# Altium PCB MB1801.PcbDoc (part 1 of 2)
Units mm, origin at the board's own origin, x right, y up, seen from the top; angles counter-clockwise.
Board outline 70.1 x 57.1 mm, 2 copper layers (Top Layer, Bottom Layer), stack 1.554 mm thick; 124 components, 115 nets, 557 pads, 485 vias.
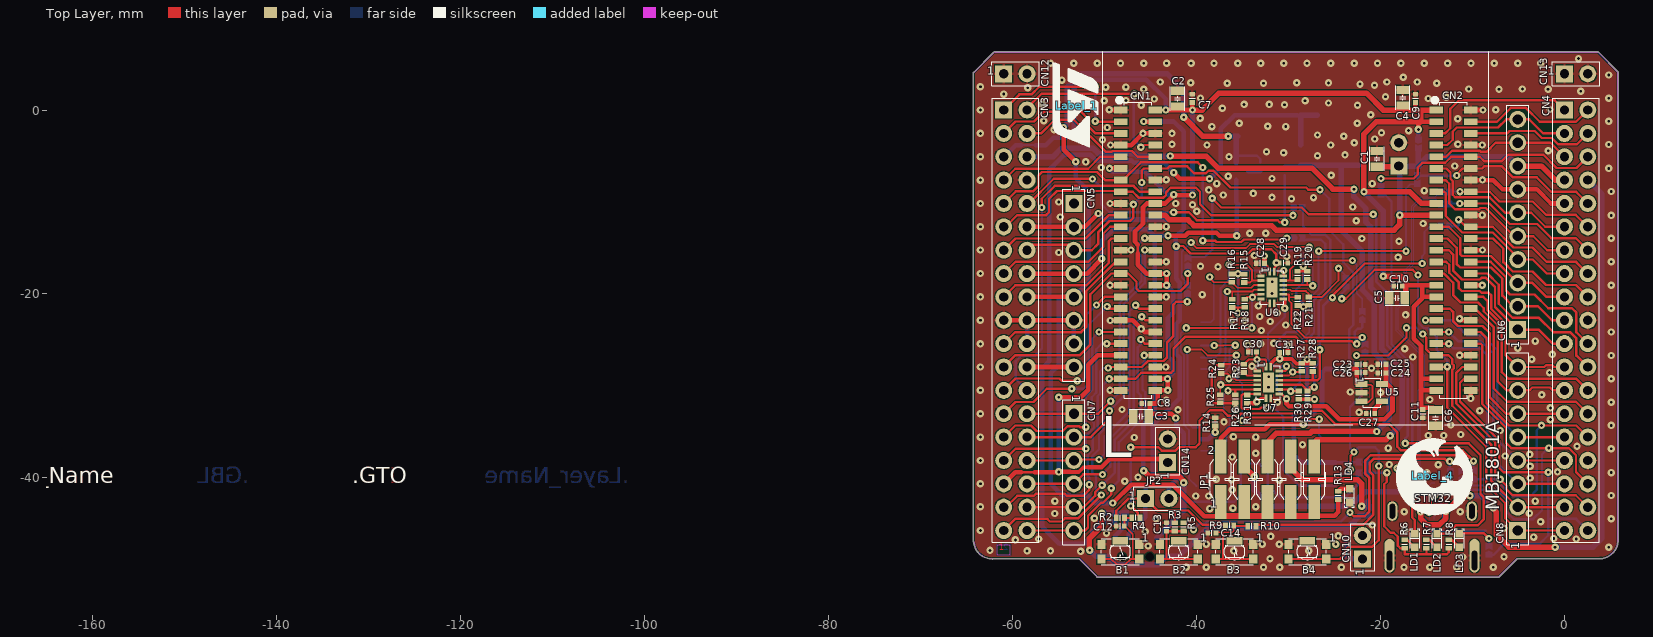
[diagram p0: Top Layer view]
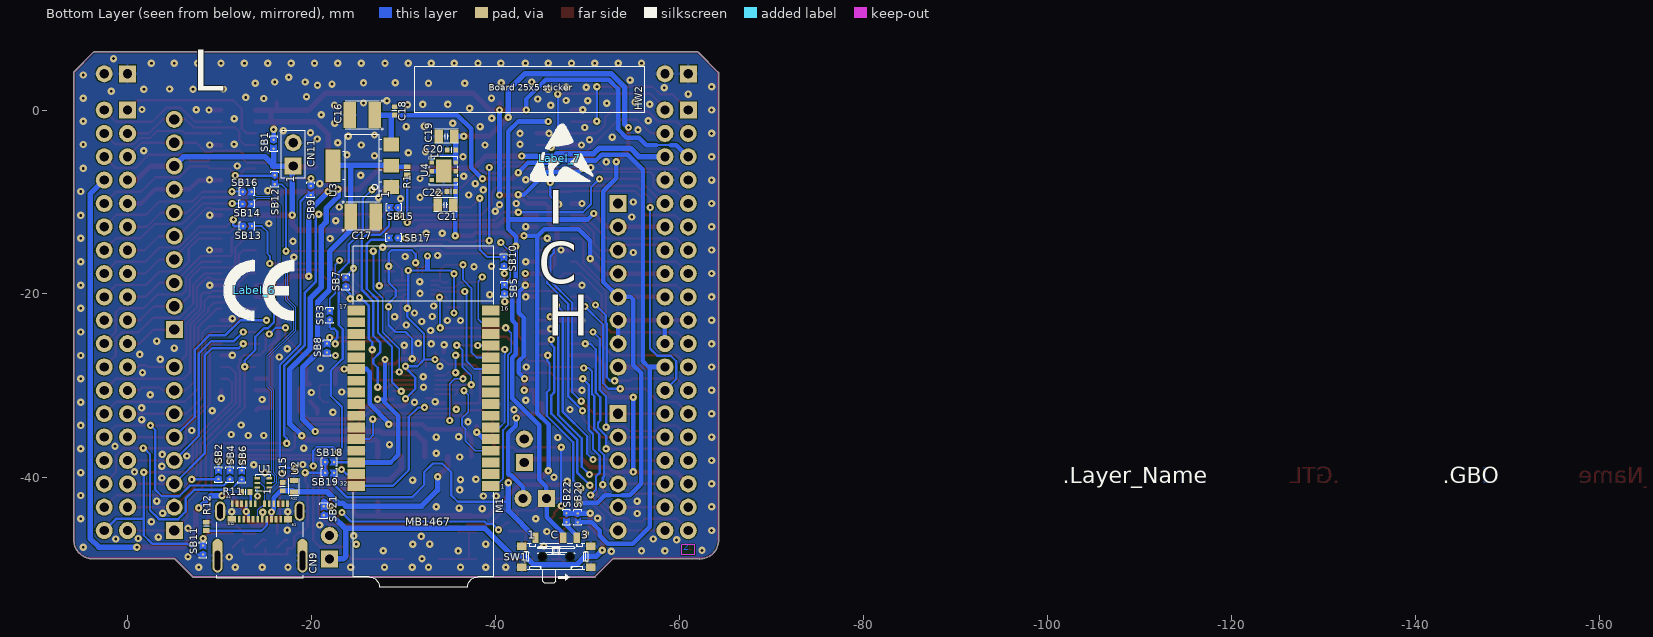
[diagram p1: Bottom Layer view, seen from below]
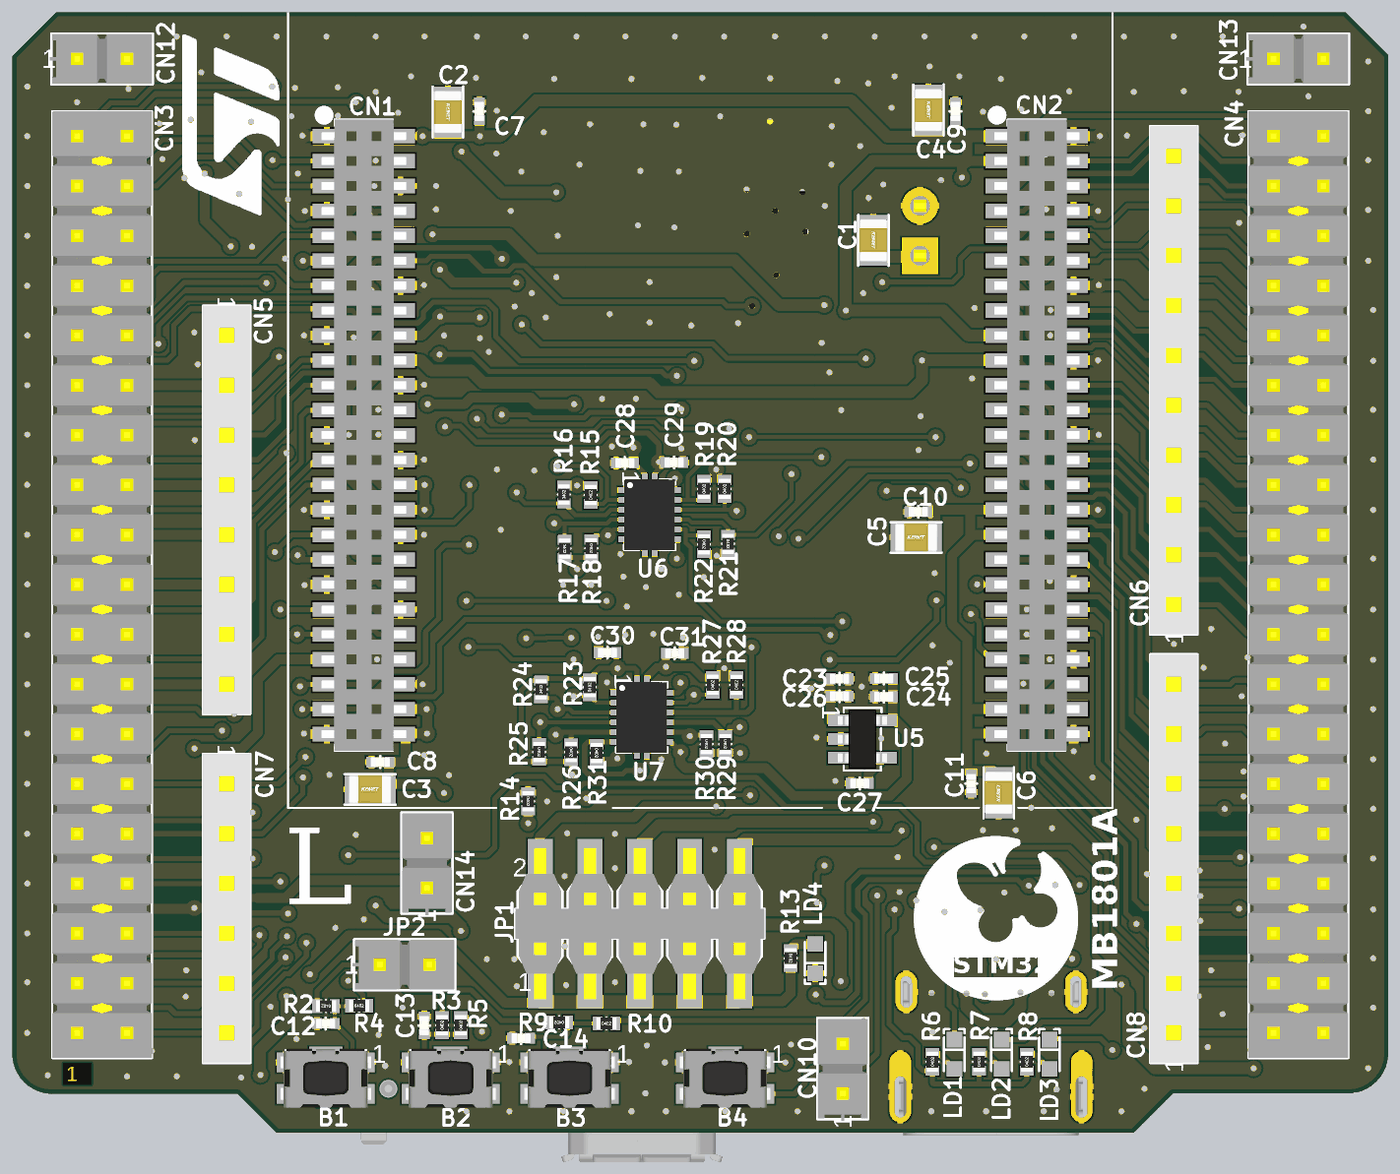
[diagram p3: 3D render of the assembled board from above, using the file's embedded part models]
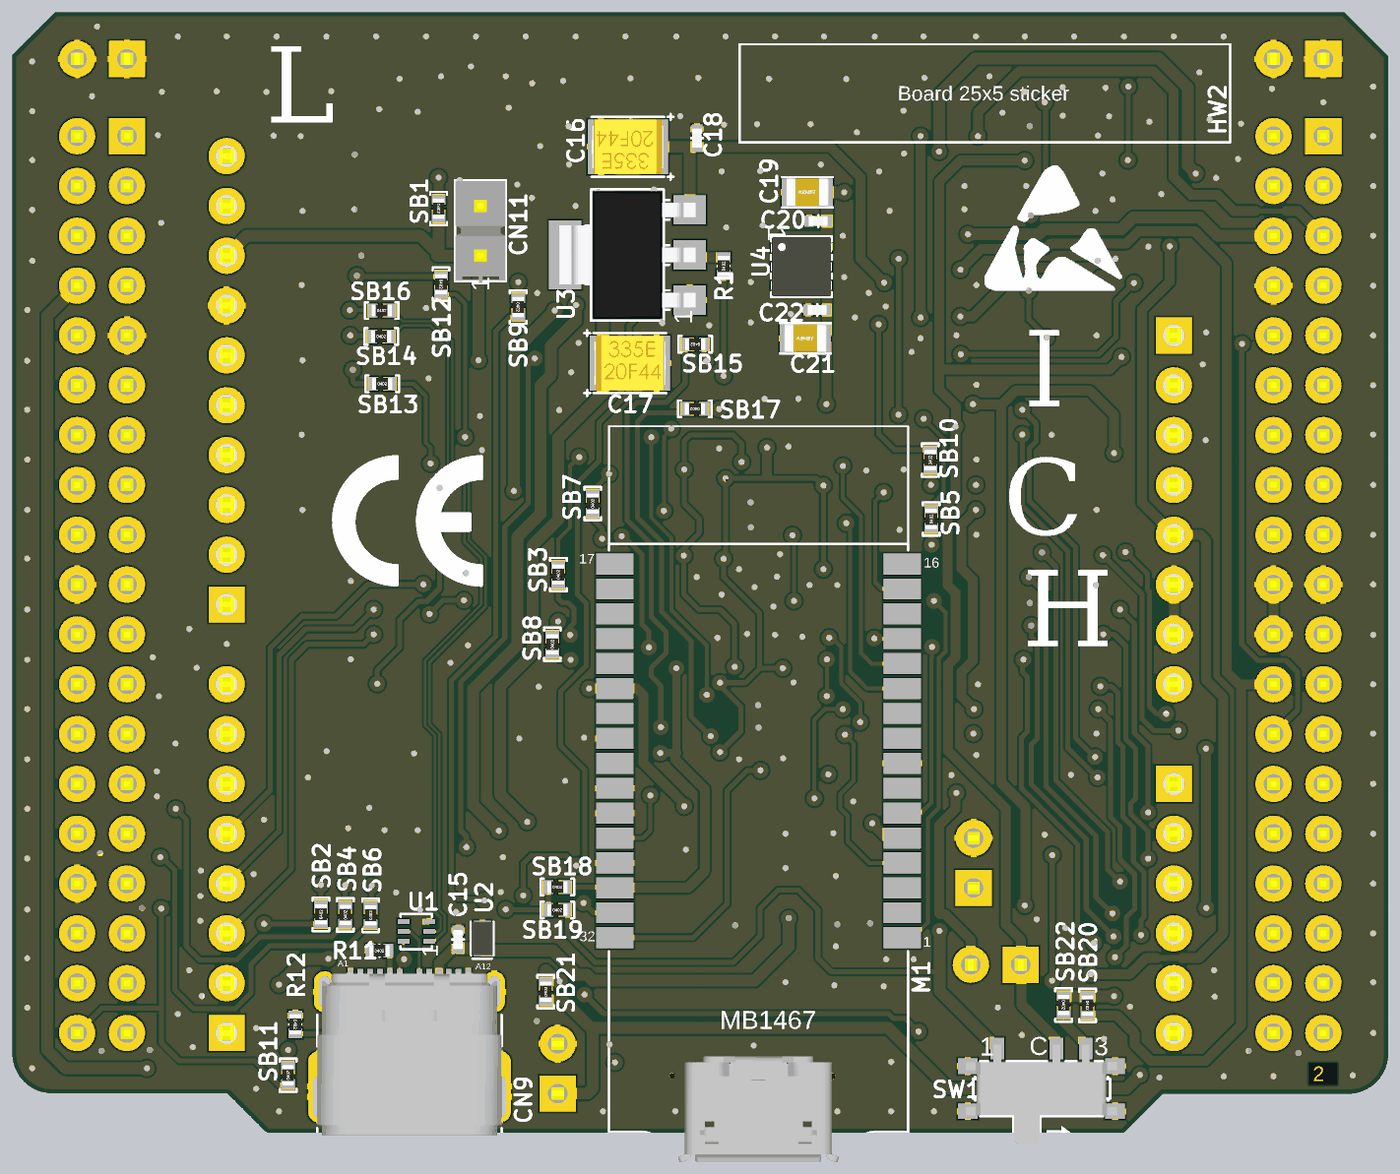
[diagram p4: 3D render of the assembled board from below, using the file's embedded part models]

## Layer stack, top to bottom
Top Solder: solder mask 0.0178, Solder Resist, Dk 4.2
Top Layer: signal copper 0.0406
Dielectric 1: dielectric 1.4732, FR-4, Dk 4.4
Bottom Layer: signal copper 0.0406
Bottom Solder: solder mask 0.0178, Solder Resist, Dk 4.2

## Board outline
-62.21,-48.818 ccw(c-62.21,-48.768) -62.183,-48.81 -52.79,-48.81 -50.822,-50.778 ccw(c-50.786,-50.743) -50.786,-50.793 -7.131,-50.793 ccw(c-7.131,-50.743) -7.095,-50.778 -5.11,-48.793 3.79,-48.793 ccw(c3.79,-46.743) 5.84,-46.743 ccw(c5.79,-46.743) 5.84,-46.742 5.84,2.211 5.84,4.125 ccw(c5.79,4.125) 5.825,4.161 5.826,4.16 3.693,6.293 3.694,6.292 ccw(c3.658,6.257) 3.658,6.307 -62.001,6.307 ccw(c-62.001,6.257) -62.037,6.292 -62.037,6.293 -64.246,4.084 -64.245,4.084 ccw(c-64.21,4.048) -64.26,4.048 -64.26,-46.768 ccw(c-64.21,-46.768) -64.26,-46.769 cw(c-62.21,-46.768) -64.26,-46.768 -64.26,-46.769 ccw(c-62.21,-46.768)

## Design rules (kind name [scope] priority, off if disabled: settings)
Clearance [All] p1: gap=0.1 ignorepadtopadclearanceinfootprint=FALSE
ComponentClearance [All] p1: gap=0.2 collisioncheckmode=3 verticalgap=0.2 showdistances=FALSE
DiffPairsRouting [All] p1: maxlimit=0.102 minlimit=0.102 mostfreqgap=0.102 toplayer_minwidth=0.12 toplayer_maxwidth=0.12 toplayer_prefwidth=0.12 bottomlayer_minwidth=0.12 bottomlayer_maxwidth=0.12 bottomlayer_prefwidth=0.12 maxuncoupledlength=12.7
HoleSize [All] p1: absolutevalues=TRUE maxlimit=10 minlimit=0.025 maxpercent=80.000 minpercent=20.000
MatchedLengths "Schematic Matched Net Lengths_3" [InNet('USB_C_N')] p1: tolerance=2 checknetsindiffpair=TRUE checkdiffpairvsdiffpair=FALSE checkxsignals=FALSE checkothers=FALSE
MatchedLengths "Schematic Matched Net Lengths_2" [InNet('USB_C_P')] p2: tolerance=2 checknetsindiffpair=TRUE checkdiffpairvsdiffpair=FALSE checkxsignals=FALSE checkothers=FALSE
MatchedLengths "Schematic Matched Net Lengths_1" [InNet('USB_P')] p3: tolerance=2 checknetsindiffpair=TRUE checkdiffpairvsdiffpair=FALSE checkxsignals=FALSE checkothers=FALSE
MatchedLengths "Schematic Matched Net Lengths" [InNet('USB_N')] p4: tolerance=2 checknetsindiffpair=TRUE checkdiffpairvsdiffpair=FALSE checkxsignals=FALSE checkothers=FALSE
MaxMinImpedance "Schematic Impedance Constraint_8" [InNet('USB_C_P')] p1: minimum=85,00 maximum=95,00
MaxMinImpedance "Schematic Impedance Constraint_7" [InNet('USB_P')] p2: minimum=85,00 maximum=95,00
MaxMinImpedance "Schematic Impedance Constraint_6" [InNet('USB_C_N')] p3: minimum=85,00 maximum=95,00
MaxMinImpedance "Schematic Impedance Constraint" [InNet('USB_N')] p4: minimum=85,00 maximum=95,00
MinimumSolderMaskSliver [All] p1: minsoldermaskwidth=0.1
PlaneConnect [All] p1: planeconnectstyle=Direct reliefexpansion=0.508 reliefentries=4 reliefconductorwidth=0.21 reliefairgap=0.21
PolygonConnect PolygonConnect_via [IsVia] p1: connectstyle=Direct reliefconductorwidth=0.254 reliefentries=4 polygonreliefangle="90 Angle" airgapwidth=0.254
PolygonConnect [All] p2: connectstyle=Relief reliefconductorwidth=0.3 reliefentries=4 polygonreliefangle="90 Angle" airgapwidth=0.1
RoutingVias [All] p1: holewidth=0.3 width=0.8 viastyle="Through Hole" minholewidth=0.3 minwidth=0.8 maxholewidth=0.3 maxwidth=0.8
SilkToSilkClearance [All] p1: silktosilkclearance=0.2
SilkToSolderMaskClearance [IsPad] p1: minsilkscreentomaskgap=0.2 clearancetoexposedcopper=TRUE
SolderMaskExpansion [All] p1: expansion=0.102 istentingtop=FALSE
Width [All] p1: maxlimit=1 minlimit=0.2 preferedwidth=0.2 minimp=50.000000 maximp=50.000000 favimp=50.000000
23 further rules are at their usual default settings.

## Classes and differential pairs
component class Project_Overview: HW1 HW2
component class "STLINK-V3MODS & Level Shifter": C23 C24 C25 C26 C27 C28 C29 C30 C31 M1 R14 R15 R16 R17 R18 R19 R20 R21 R22 R23 R24 R25 R26 R27 R28 R29 R30 R31 U5 U6 U7
component class "Power Management": C16 C17 C18 C19 C20 C21 C22 CN10 CN12 CN13 HW1 JP1 JP2 LD4 R13 SB20 SB21 SB22 SW1 U3 U4
component class "LEDs & Push Buttons & USB-C Connector": B1 B2 B3 B4 C12 C13 C14 C15 CN9 LD1 LD2 LD3 R2 R3 R4 R5 R6 R7 R8 R9 R10 R11 R12 SB18 SB19 U1 U2
component class "Extension Connectors": C1 C2 C3 C4 C5 C6 C7 C8 C9 C10 C11 CN1 CN2 CN3 CN4 CN5 CN6 CN7 CN8 CN11 CN14 R1 SB1 SB2 SB3 SB4 SB5 SB6 SB7 SB8 SB9 SB10 SB11 SB12 SB13 SB14 SB15 SB16 SB17
differential pair USB: +USB_P -USB_N
differential pair USB_C: +USB_C_P -USB_C_N

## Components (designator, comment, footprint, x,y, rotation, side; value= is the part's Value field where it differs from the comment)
B1 "SW-PUSH-CMS_KMR2_BLACK" SWI_C&K_Y78B23110FP__ITT_KMR231GLFS -48.29,-48.022 r0 top value=KMR231GLFS
B2 "SW-PUSH-CMS_KMR2_BLACK" SWI_C&K_Y78B23110FP__ITT_KMR231GLFS -41.93,-48.022 r0 top value=KMR231GLFS
B3 "SW-PUSH-CMS_KMR2_BLACK" SWI_C&K_Y78B23110FP__ITT_KMR231GLFS -35.871,-48.022 r0 top locked value=KMR231GLFS
B4 "SW-PUSH-CMS_KMR2_BLACK" SWI_C&K_Y78B23110FP__ITT_KMR231GLFS -27.946,-48.022 r0 top locked value=KMR231GLFS
C1 "Capacitor" C0805_H0P85 -20.387,-5.308 r270 top value=1uF
C2 "Capacitor" C0805_H0P85 -42.066,1.23 r270 top value=1uF
C3 "Capacitor" C0805_H0P85 -46.035,-33.303 r0 top value=1uF
C4 "Capacitor" C0805_H0P85 -17.58,1.331 r270 top value=1uF
C5 "Capacitor" C0805_H0P85 -18.207,-20.457 r0 top value=1uF
C6 "Capacitor" C0805_H0P85 -13.999,-33.472 r90 top value=1uF
C7 "Capacitor" C0402 -40.464,1.268 r270 top value=100nF
C8 "Capacitor" C0402 -45.514,-31.904 r0 top value=100nF
C9 "Capacitor" C0402 -16.207,1.268 r270 top value=100nF
C10 "Capacitor" C0402 -18.1,-19.146 r0 top value=100nF
C11 "Capacitor" C0402 -15.403,-33.003 r90 top value=100nF
C12 "Capacitor" C0402 -48.293,-45.236 r0 top value=10nF
C13 "Capacitor" C0402 -43.272,-45.336 r270 top value=10nF
C14 "Capacitor" C0402 -38.339,-45.984 r0 top value=10nF
C15 "Capacitor" C0402 -16.87,-40.95 r270 bottom value=100pF
C16 "Cap_POL_TANA" CPOL_TAJ-B_1210_H210 -25.521,-0.546 r0 bottom value=10uF
C17 "Cap_POL_TANA" CPOL_TAJ-B_1210_H210 -25.621,-11.567 r180 bottom value=10uF
C18 "Capacitor" C0402 -29.046,-0.101 r270 bottom value=100nF
C19 "Capacitor" C0805_H0P85 -34.671,-2.864 r180 bottom value=1uF
C20 "Capacitor" C0402 -35.221,-4.332 r180 bottom value=100nF
C21 "Capacitor" C0805_H0P85 -34.569,-10.308 r180 bottom value=1uF
C22 "Capacitor" C0402 -35.171,-8.859 r180 bottom value=100nF
C23 "Capacitor" C0402 -22.113,-27.661 r180 top value=1uF
C24 "Capacitor" C0402 -19.852,-28.575 r0 top value=1uF
C25 "Capacitor" C0402 -19.852,-27.643 r0 top value=100nF
C26 "Capacitor" C0402 -22.113,-28.55 r180 top value=100nF
C27 "Capacitor" C0402 -21.082,-32.995 r0 top value=100nF
C28 "Capacitor" C0402 -33.049,-16.656 r180 top value=100nF
C29 "Capacitor" C0402 -30.54,-16.63 r180 top value=100nF
C30 "Capacitor" C0402 -33.935,-26.327 r180 top value=100nF
C31 "Capacitor" C0402 -30.51,-26.362 r180 top value=100nF
CN1 "CLP-125-02-F-D" CLP-125-02-F-D -46.355,-15.24 r0 top locked
CN2 "CLP-125-02-F-D" CLP-125-02-F-D -12.065,-15.24 r0 top locked
CN3 "Header 19x2" CON_SAMTEC_TSW-119-09-X-D -59.69,-22.86 r270 top locked
CN4 "Header 19x2" CON_SAMTEC_TSW-119-09-X-D 1.27,-22.86 r270 top locked
CN5 "Socket 8x1" CON_SAMTEC_SSW-108-01-X-S -53.34,-19.05 r270 top locked
CN6 "Socket 10x1" CON_SAMTEC_SSW-110-01-X-S -5.08,-12.446 r90 top locked
CN7 "Socket 6x1" CON_SAMTEC_SSW-106-01-X-S -53.34,-39.37 r270 top locked
CN8 "Socket 8x1" CON_SAMTEC_SSW-108-01-X-S -5.08,-36.83 r90 top locked
CN9 "USB_TYPE_C_Receptacle" CON_USB-TYPEC_MOLEX_2012670005 -14.392,-45.892 r180 bottom value=USB_C_2012670005
CN10 "Header 2x1" CON_SAMTEC_TSW-102-07-G-S -21.949,-47.535 r90 top
CN11 "Header 2x1" CON_SAMTEC_TSW-102-07-G-S -18.013,-4.823 r90 bottom
CN12 "Header 2x1" CON_SAMTEC_TSW-102-07-G-S -59.69,3.937 r0 top
CN13 "Header 2x1" CON_SAMTEC_TSW-102-07-G-S 1.27,3.937 r0 top locked
CN14 "Header 2x1" CON_SAMTEC_TSW-102-07-G-S -43.135,-37.049 r90 top
HW2 "STICKER_BOARD" STICKER_BOARD_25X5 -43.711,2.183 r180 bottom value="Sticker board"
JP1 "Jumper_Header 5x2 Fitted 1-2" CON_SAMTEC_TSM-105-01-L-DV -32.288,-40.146 r0 top value="Header 5x2"
JP2 "Jumper_Header 2x1 Fitted" CON_SAMTEC_TSW-102-07-G-S -44.271,-42.237 r0 top value="Header 2x1"
Label_1 "LOGO_ST" LOGO_ST_Size3 -53.029,0.465 r90 top
Label_4 "LOGO_STM32" LOGO_STM32 -14.298,-39.75 r0 top
Label_6 "LOGO_CE" "LOGO CE" -13.764,-19.607 r180 bottom
Label_7 "LOGO_ESD" "LOGO ESD" -46.982,-5.223 r180 bottom
LD1 "LED_blue" LED_0603_VISHAY_VLMB1300-GS08_BLUE_1A2K_H0P8 -16.266,-46.8 r90 top value=BLUE
LD2 "LED_green" LED_0603_VISHAY_VLMTG1300-GS08_GREEN_1A2K_H0P8 -13.852,-46.8 r90 top value="TRUE GREEN"
LD3 "LED_red" LED_0603_VISHAY_VLMS1300-GS08_RED_1A2K_H0P8 -11.424,-46.8 r90 top value=RED
LD4 "LED_green" LED_0603_VISHAY_VLMTG1300-GS08_GREEN_1A2K_H0P8 -23.355,-41.931 r270 top value="TRUE GREEN"
M1 "STLINK-V3MODS" MOD_STLINK-V3M_MB1467_TYPEC -32.178,-31.334 r180 bottom locked
R1 "Resistor" R0402 -30.397,-6.623 r90 bottom value=1K
R2 "Resistor" R0402 -48.278,-44.343 r180 top value=10K
R3 "Resistor" R0402 -42.365,-45.321 r90 top value=10K
R4 "Resistor" R0402 -46.591,-44.324 r0 top value=1K
R5 "Resistor" R0402 -41.408,-45.319 r90 top value=1K
R6 "Resistor" R0402 -17.374,-47.185 r90 top value=680R
R7 "Resistor" R0402 -15.006,-47.184 r90 top value=680R
R8 "Resistor" R0402 -12.577,-47.185 r90 top value=680R
R9 "Resistor" R0402 -36.398,-45.173 r180 top value=10K
R10 "Resistor" R0402 -33.989,-45.232 r0 top value=1K
R11 "Resistor" R0402 -12.865,-41.53 r180 bottom value=5K1
R12 "Resistor" R0402 -8.57,-45.275 r270 bottom value=5K1
R13 "Resistor" R0402 -24.6,-41.902 r270 top value=1K
R14 "Resistor" R0402 -37.978,-33.907 r270 top value=100R
R15 "Resistor" R0402 -34.796,-18.293 r90 top value=100K
R16 "Resistor" R0402 -36.158,-18.268 r90 top value=100K
R17 "Resistor" R0402 -36.122,-21.024 r270 top value=100K
R18 "Resistor" R0402 -34.76,-21.009 r270 top value=100K
R19 "Resistor" R0402 -29.021,-17.977 r90 top value=100K
R20 "Resistor" R0402 -27.969,-17.978 r90 top value=100K
R21 "Resistor" R0402 -27.793,-20.782 r270 top value=100K
R22 "Resistor" R0402 -29.015,-20.807 r270 top value=100K
R23 "Resistor" R0402 -34.846,-28.092 r90 top value=100K
R24 "Resistor" R0402 -37.329,-28.201 r90 top value=100K
R25 "Resistor" R0402 -37.417,-31.392 r270 top value=100K
R26 "Resistor" R0402 -35.784,-31.401 r270 top value=100K
R27 "Resistor" R0402 -28.58,-27.967 r90 top value=100K
R28 "Resistor" R0402 -27.374,-27.976 r90 top value=100K
R29 "Resistor" R0402 -27.935,-30.992 r270 top value=100K
R30 "Resistor" R0402 -28.889,-30.992 r270 top value=100K
R31 "Resistor" R0402 -34.491,-31.442 r270 top value=100K
SB1 "SB_ON" SOLDER-BRIDGE_R0402-0R -15.878,-3.692 r270 bottom
SB2 "SB_ON" SOLDER-BRIDGE_R0402-0R -9.884,-39.672 r90 bottom
SB3 "SB_ON" SOLDER-BRIDGE_R0402-0R -21.98,-22.35 r90 bottom
SB4 "SB_ON" SOLDER-BRIDGE_R0402-0R -11.123,-39.697 r90 bottom
SB5 "SB_ON" SOLDER-BRIDGE_R0402-0R -40.979,-19.516 r90 bottom
SB6 "SB_ON" SOLDER-BRIDGE_R0402-0R -12.416,-39.718 r90 bottom
SB7 "SB_OFF" SOLDER-BRIDGE_R0402-0R -23.733,-18.729 r90 bottom value=SB0402
SB8 "SB_OFF" SOLDER-BRIDGE_R0402-0R -21.675,-25.904 r90 bottom value=SB0402
SB9 "SB_ON" SOLDER-BRIDGE_R0402-0R -19.932,-8.712 r270 bottom
SB10 "SB_ON" SOLDER-BRIDGE_R0402-0R -40.931,-16.513 r90 bottom
SB11 "SB_ON" SOLDER-BRIDGE_R0402-0R -8.211,-47.869 r90 bottom
SB12 "SB_OFF" SOLDER-BRIDGE_R0402-0R -16.002,-7.544 r270 bottom value=SB0402
SB13 "SB_OFF" SOLDER-BRIDGE_R0402-0R -13.005,-12.624 r180 bottom value=SB0402
SB14 "SB_OFF" SOLDER-BRIDGE_R0402-0R -12.954,-10.211 r180 bottom value=SB0402
SB15 "SB_ON" SOLDER-BRIDGE_R0402-0R -28.956,-10.608 r0 bottom
SB16 "SB_OFF" SOLDER-BRIDGE_R0402-0R -12.979,-8.89 r180 bottom value=SB0402
SB17 "SB_ON" SOLDER-BRIDGE_R0402-0R -28.936,-13.901 r0 bottom
SB18 "SB_ON" SOLDER-BRIDGE_R0402-0R -21.93,-38.278 r180 bottom
SB19 "SB_OFF" SOLDER-BRIDGE_R0402-0R -21.93,-39.446 r180 bottom value=SB0402
SB20 "SB_OFF" SOLDER-BRIDGE_R0402-0R -48.943,-44.311 r270 bottom value=SB0402
SB21 "SB_OFF" SOLDER-BRIDGE_R0402-0R -21.339,-43.61 r90 bottom value=SB0402
SB22 "SB_OFF" SOLDER-BRIDGE_R0402-0R -47.724,-44.29 r270 bottom value=SB0402
SW1 "SW_MECA" SWI_SPDT-RA_TE-CONNECTIVITY_MLL1200S_1P2T -46.6,-48.559 r180 bottom locked value=Switch-Slider_3x1_MLL1200S
U1 "ECMF02-2AMX6" ESD_QFN-6L_1P7X1P5_P050 -14.741,-40.55 r90 bottom
U2 "ESD-TRANSIL" ESD_QFN1610_2N_1K_2A -18.1,-40.9 r90 bottom value=ESDA25P35-1U1M
U3 "LD1117S50TR" REG_SOT223-TAB -25.496,-6.057 r90 bottom
U4 "LD39050PU33R" ICC_DFN6-EPAD_3X3_P095 -34.371,-6.655 r270 bottom
U5 "LD3985M33R" REG_SOT23-5L -20.948,-30.738 r270 top
U6 "74AVC4TD245BQ" ICC_DHVQFN16-EPAD_SOT763-1_2P5X3P5_H0P85_P050 -31.79,-19.291 r0 top
U7 "74AVC4TD245BQ" ICC_DHVQFN16-EPAD_SOT763-1_2P5X3P5_H0P85_P050 -32.19,-29.63 r0 top
? "Comment" PCB_SPECIFICATIONS -182.118,65.278 r0 top
? "Comment" Sheetbox_2L2S -182.474,-52.857 r0 top

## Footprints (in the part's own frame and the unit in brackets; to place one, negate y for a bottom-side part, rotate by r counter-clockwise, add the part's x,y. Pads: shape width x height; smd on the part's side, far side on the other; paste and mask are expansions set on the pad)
C0402 [mm]
  rect 0.51x0.56 smd mask+0.05: 1(-0.45,0) 2(0.45,0)
  silkscreen extent 0,-0.3 0,0.3, body extent -0.5,-0.3 0.5,0.3, height 0.4
C0805_H0P85 [mm] "MCD-01525"
  rect 0.9x1.4 smd mask+0.05: 1(-0.85,0) 2(0.85,0)
  silkscreen extent -1.3,-0.77 1.3,0.77, body extent -1.1,-0.73 1.1,0.73, height 0.95
CLP-125-02-F-D [mm] "Socket 2x25 1.27mm SAMTEC (CLP-125-02-F-D)"
  rect 1.47x0.74 smd: 1(-1.87,15.24) 2(1.87,15.24) 3(-1.87,13.97) 4(1.87,13.97) 5(-1.87,12.7) 6(1.87,12.7) 7(-1.87,11.43) 8(1.87,11.43) 9(-1.87,10.16) 10(1.87,10.16) 11(-1.87,8.89) 12(1.87,8.89) 13(-1.87,7.62) 14(1.87,7.62) 15(-1.87,6.35) 16(1.87,6.35) 17(-1.87,5.08) 18(1.87,5.08) 19(-1.87,3.81) 20(1.87,3.81) 21(-1.87,2.54) 22(1.87,2.54) 23(-1.87,1.27) 24(1.87,1.27) 25(-1.87,0) 26(1.87,0) 27(-1.87,-1.27) 28(1.87,-1.27) 29(-1.87,-2.54) 30(1.87,-2.54) 31(-1.87,-3.81) 32(1.87,-3.81) 33(-1.87,-5.08) 34(1.87,-5.08) 35(-1.87,-6.35) 36(1.87,-6.35) 37(-1.87,-7.62) 38(1.87,-7.62) 39(-1.87,-8.89) 40(1.87,-8.89) 41(-1.87,-10.16) 42(1.87,-10.16) 43(-1.87,-11.43) 44(1.87,-11.43) 45(-1.87,-12.7) 46(1.87,-12.7) 47(-1.87,-13.97) 48(1.87,-13.97) 49(-1.87,-15.24) 50(1.87,-15.24)
  silkscreen extent -2.25,-16.09 1.49,16.54, body extent -2.15,-16.09 2.17,16.09, height 2.27
CON_SAMTEC_SSW-106-01-X-S [mm] "MCD-02079"
  rect 1.85x1.85 / inner round 1.85 / far side rect 1.85x1.85 hole 1.1 mask+0.05: 1(-6.35,0)
  round 1.85 hole 1.1 mask+0.05: 2(-3.81,0) 3(-1.27,0) 4(1.27,0) 5(3.81,0) 6(6.35,0)
  silkscreen extent -7.88,-1.2 7.88,1.2, body extent -7.88,-1.21 7.88,1.21, height 8.51
CON_SAMTEC_SSW-108-01-X-S [mm] "MCD-01743"
  rect 1.85x1.85 / inner round 1.85 / far side rect 1.85x1.85 hole 1.1 mask+0.05: 1(-8.89,0)
  round 1.85 hole 1.1 mask+0.05: 2(-6.35,0) 3(-3.81,0) 4(-1.27,0) 5(1.27,0) 6(3.81,0) 7(6.35,0) 8(8.89,0)
  silkscreen extent -10.42,-1.2 10.42,1.2, body extent -10.42,-1.21 10.42,1.21, height 8.51
CON_SAMTEC_SSW-110-01-X-S [mm] "MCD-02080"
  rect 1.85x1.85 / inner round 1.85 / far side rect 1.85x1.85 hole 1.1 mask+0.05: 1(-11.43,0)
  round 1.85 hole 1.1 mask+0.05: 2(-8.89,0) 3(-6.35,0) 4(-3.81,0) 5(-1.27,0) 6(1.27,0) 7(3.81,0) 8(6.35,0) 9(8.89,0) 10(11.43,0)
  silkscreen extent -12.96,-1.2 12.96,1.2, body extent -12.96,-1.21 12.96,1.21, height 8.51
CON_SAMTEC_TSM-105-01-L-DV [mm]
  rect 1.27x3.68 smd paste+0 mask+0.05: 1(-5.08,-2.475) 2(-5.08,2.475) 3(-2.54,-2.475) 4(-2.54,2.475) 5(0,-2.475) 6(0,2.475) 7(2.54,-2.475) 8(2.54,2.475) 9(5.08,-2.475) 10(5.08,2.475)
  silkscreen extent -6.35,-2.16 6.35,2.16, body extent -6.35,-3.85 6.35,3.85, height 9.65
CON_SAMTEC_TSW-102-07-G-S [mm]
  rect 1.85x1.85 / inner round 1.85 / far side rect 1.85x1.85 hole 1 mask+0.05: 1(-1.27,0)
  round 1.85 hole 1 mask+0.05: 2(1.27,0)
  silkscreen extent -2.58,-1.3 2.58,1.3, body extent -2.67,-1.3 2.58,1.3, height 8.38
CON_SAMTEC_TSW-119-09-X-D [mm]
  rect 1.85x1.85 / inner round 1.85 / far side rect 1.85x1.85 hole 1 mask+0.05: 1(-22.86,-1.27)
  round 1.85 hole 1 mask+0.05: 2(-22.86,1.27) 3(-20.32,-1.27) 4(-20.32,1.27) 5(-17.78,-1.27) 6(-17.78,1.27) 7(-15.24,-1.27) 8(-15.24,1.27) 9(-12.7,-1.27) 10(-12.7,1.27) 11(-10.16,-1.27) 12(-10.16,1.27) 13(-7.62,-1.27) 14(-7.62,1.27) 15(-5.08,-1.27) 16(-5.08,1.27) 17(-2.54,-1.27) 18(-2.54,1.27) 19(0,-1.27) 20(0,1.27) 21(2.54,-1.27) 22(2.54,1.27) 23(5.08,-1.27) 24(5.08,1.27) 25(7.62,-1.27) 26(7.62,1.27) 27(10.16,-1.27) 28(10.16,1.27) 29(12.7,-1.27) 30(12.7,1.27) 31(15.24,-1.27) 32(15.24,1.27) 33(17.78,-1.27) 34(17.78,1.27) 35(20.32,-1.27) 36(20.32,1.27) 37(22.86,-1.27) 38(22.86,1.27)
  silkscreen extent -24.13,-2.54 24.13,2.54, body extent -24.13,-2.55 24.13,2.54, height 8.38
CON_USB-TYPEC_MOLEX_2012670005 [mm] "MCD-02421"
  rect 0.3x0.7 smd mask+0.05: A1(-3,3.085) A2(-2.5,3.085) A3(-2,3.085) A4(-1.5,3.085) A5(-1,3.085) A6(-0.5,3.085) A7(0.5,3.085) A8(1,3.085) A9(1.5,3.085) A10(2,3.085) A11(2.5,3.085) A12(3,3.085) B2(2.25,1.385) B3(1.75,1.385) B4(1.25,1.385) B5(0.75,1.385) B6(0.25,1.385) B7(-0.25,1.385) B8(-0.75,1.385) B9(-1.25,1.385) B10(-1.75,1.385) B11(-2.25,1.385)
  rect 0.9x0.7 smd mask+0.05: B1(3.05,1.385) B12(-3.05,1.385)
  oval 1.1x2.1 hole 0.6 slot 1.6 at 90 deg mask+0.05: SH1(-4.32,2.275) SH2(4.32,2.275)
  oval 1.1x2.6 hole 0.6 slot 2.1 at 90 deg mask+0.05: SH3(-4.62,-3.085) SH4(4.62,-3.085)
  oval 1.1x3.6 all layers, no hole mask+0.05: SH3(-4.62,-2.55) SH4(4.62,-2.55)
  silkscreen extent -4.7,-5.02 4.7,1.1, body extent -4.7,-5.03 4.69,3.27, height 3.67
CPOL_TAJ-B_1210_H210 [mm]
  rect 1.35x2.8 smd mask+0.05: 1(-1.375,0) 2(1.375,0)
  silkscreen extent -2.33,-1.68 1.85,1.68, body extent -1.85,-1.5 1.85,1.5, height 2.11
ESD_QFN1610_2N_1K_2A [mm] "DFN, 2-Leads, Body 1.60x1.00mm"
  rect 0.55x0.9 smd mask+0.05: 1(-0.625,0) 2(0.625,0)
  silkscreen extent -1.02,-0.58 0.85,0.58, body extent -0.85,-0.55 0.85,0.55, height 0.6
ESD_QFN-6L_1P7X1P5_P050 [mm]
  rect 0.25x0.6 smd mask+0.05: 1(-0.5,-0.65) 2(0,-0.65) 3(0.5,-0.65) 4(0.5,0.65) 5(0,0.65) 6(-0.5,0.65)
  silkscreen extent -0.9,-0.8 0.9,0.8, body extent -0.9,-0.8 0.9,0.8, height 0.56
ICC_DFN6-EPAD_3X3_P095 [mm]
  rect 0.45x0.5 smd mask+0.05: 1(-0.95,-1.3) 2(0,-1.3) 3(0.95,-1.3) 4(0.95,1.3) 5(0,1.3) 6(-0.95,1.3)
  rect 2.5x1.7 smd mask+0.05: EP(0,0)
  silkscreen extent -1.55,-1.55 1.55,1.55, body extent -1.55,-1.55 1.55,1.55, height 1
ICC_DHVQFN16-EPAD_SOT763-1_2P5X3P5_H0P85_P050 [mm] "MCD-01945"
  rect 0.3x0.8 smd mask+0.05: 1(-0.25,1.7) 8(-0.25,-1.7) 9(0.25,-1.7) 16(0.25,1.7)
  rect 0.8x0.3 smd mask+0.05: 2(-1.2,1.25) 3(-1.2,0.75) 4(-1.2,0.25) 5(-1.2,-0.25) 6(-1.2,-0.75) 7(-1.2,-1.25) 10(1.2,-1.25) 11(1.2,-0.75) 12(1.2,-0.25) 13(1.2,0.25) 14(1.2,0.75) 15(1.2,1.25)
  rect 1.2x2.2 smd mask+0.05: 17(0,0)
  silkscreen extent -1.3,-1.8 1.3,1.8, body extent -1.31,-1.81 1.31,1.81, height 1.01
LED_0603_VISHAY_VLMB1300-GS08_BLUE_1A2K_H0P8 [mm]
  rect 0.8x0.8 smd mask+0.05: 1(-0.75,0) 2(0.75,0)
  silkscreen extent -0.85,-0.53 1.28,0.53, body extent -0.85,-0.45 0.85,0.45, height 0.8
LED_0603_VISHAY_VLMS1300-GS08_RED_1A2K_H0P8 [mm]
  rect 0.8x0.8 smd mask+0.05: 1(-0.75,0) 2(0.75,0)
  silkscreen extent -0.85,-0.53 1.28,0.53, body extent -0.85,-0.45 0.85,0.45, height 0.8
LED_0603_VISHAY_VLMTG1300-GS08_GREEN_1A2K_H0P8 [mm]
  rect 0.8x0.8 smd mask+0.05: 1(-0.75,0) 2(0.75,0)
  silkscreen extent -0.85,-0.53 1.28,0.53, body extent -0.85,-0.45 0.85,0.45, height 0.8
"LOGO CE" [mm]
  silkscreen extent -3.27,-3.31 4.33,3.3
"LOGO ESD" [mm]
  silkscreen extent -3.23,-2.59 3.66,3.68
LOGO_ST_Size3 [mm]
  silkscreen extent -4.5,-2.36 4.7,2.57
LOGO_STM32 [mm]
  silkscreen extent -3.9,-4.23 4.33,3.95
MOD_STLINK-V3M_MB1467_TYPEC [mm] "STLINK-V3MODS, MB1467 with reserved area to be compatible with Type-C version"
  rect 1.9x1.07 smd paste+0 mask+0.05: 1(7.32,-9.525) 2(7.32,-8.255) 3(7.32,-6.985) 4(7.32,-5.715) 5(7.32,-4.445) 6(7.32,-3.175) 7(7.32,-1.905) 8(7.32,-0.635) 9(7.32,0.635) 10(7.32,1.905) 11(7.32,3.175) 12(7.32,4.445) 13(7.32,5.715) 14(7.32,6.985) 15(7.32,8.255) 16(7.32,9.525) 17(-7.32,9.525) 18(-7.32,8.255) 19(-7.32,6.985) 20(-7.32,5.715) 21(-7.32,4.445) 22(-7.32,3.175) 23(-7.32,1.905) 24(-7.32,0.635) 25(-7.32,-0.635) 26(-7.32,-1.905) 27(-7.32,-3.175) 28(-7.32,-4.445) 29(-7.32,-5.715) 30(-7.32,-6.985) 31(-7.32,-8.255) 32(-7.32,-9.525)
  silkscreen extent -7.62,-20.53 7.62,16.54, body extent -7.62,-20.98 7.62,16.56, height 4.23
PCB_SPECIFICATIONS [mm]
R0402 [mm]
  rect 0.51x0.7 smd mask+0.05: 1(-0.45,0) 2(0.45,0)
  silkscreen extent 0,-0.3 0,0.3, body extent -0.52,-0.3 0.52,0.3, height 0.4
REG_SOT23-5L [mm]
  rect 0.6x1.3 smd mask+0.05: 1(-0.95,-1.1) 2(0,-1.1) 3(0.95,-1.1) 4(0.95,1.1) 5(-0.95,1.1)
  silkscreen extent -1.6,-0.95 1.6,0.97, body extent -1.52,-1.25 1.52,1.25, height 1.1
REG_SOT223-TAB [mm]
  rect 1.5x1.65 smd mask+0.05: 1(-2.3,-3.175) 2(0,-3.175) 3(2.3,-3.175)
  rect 3.5x1.65 smd mask+0.05: 4(0,3.175)
  silkscreen extent -3.35,-2.15 3.35,2.12, body extent -3.35,-3.48 3.35,3.48, height 1.8
Sheetbox_2L2S [mil] "Sheetbox 2 layers / 2 silkscreens"
  round 20 on Mech16: 1(813.78,210.69) 1(2736.9,210.69)
SOLDER-BRIDGE_R0402-0R [mil] "MCD-01619"
  round 10 smd paste-393.7: 1(-17.72,0) 2(20.67,0)
  Top Layer region: 1.48,13.78 8.37,0 1.48,-13.78 30.51,-13.78 30.51,13.78
  Top Layer region: -30.51,-13.78 -30.51,13.78 -8.37,13.78 -1.48,0 -8.37,-13.78
  silkscreen extent -33,-17 33,17, body extent -20,-12 20,12, height 14
STICKER_BOARD_25X5 [mm] "Sticker to mention board reference + serial number"
  silkscreen extent -12.5,-2.5 12.5,2.5, body extent -12.5,-2.5 12.5,2.5, height 0.01
SWI_C&K_Y78B23110FP__ITT_KMR231GLFS [mm] "MCD-00715"
  rect 0.9x1 smd mask+0.05: 1(2.05,0.8) 2(2.05,-0.8) 3(-2.05,0.8) 4(-2.05,-0.8)
  rect 1.7x0.8 smd mask+0.05: 5(0,1.2)
  silkscreen extent -2.05,-1.43 2.05,1.43, body extent -2.3,-1.5 2.3,1.5, height 2.1
SWI_SPDT-RA_TE-CONNECTIVITY_MLL1200S_1P2T [mm] "MCD-02081"
  rect 1x0.8 smd mask+0.05: 0(-3.75,-1.15) 0(-3.75,1.15) 0(3.75,-1.15) 0(3.75,1.15)
  rect 0.7x1.1 smd mask+0.05: 1(-2.25,2.05) 2(0.75,2.05) 3(2.25,2.05)
  round 0 hole 0.9 unplated mask+0.05: NPTH1(-1.5,0) NPTH2(1.5,0)
  silkscreen extent -3.5,-2.9 3.5,1.4, body extent -3.85,-2.9 3.85,2.24, height 1.75

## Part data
B1 B2 B3 B4: library part MCD-01485, "Microminiature Tact Switch for SMT - KMR 2 Series - 1.9 mm height", Manufacturer=C&K, Manufacturer_Part_Number=KMR231GLFS
C1 C2 C3 C4 C5 C6 C19 C21: library part MCD-01550, "Capacitor, MLCC, 1uF, 16V, X5R, +/-10%, 0805, T=0.85mm", Manufacturer=YAGEO, Manufacturer_Part_Number=CC0805KRX5R7BB105, Package=0805
C7 C8 C9 C10 C11 C18 C20 C22 C25 C26 C27 C28 C29 C30 C31: library part MCD-02355, "Capacitor, MLCC, 100nF, 25V, X7R, +/-10%, 0402, T=0.5mm", Manufacturer=WALSIN, Manufacturer_Part_Number=0402B104K250CT, Package=0402
C12 C13 C14: library part MCD-02198, "Capacitor, MLCC, 10nF, 50V, X7R, +/-10%, 0402, T=0.5mm", Manufacturer=YAGEO, Manufacturer_Part_Number=CC0402KRX7R9BB103, Package=0402
C15: library part MCD-00205, "Capacitor, MLCC, 100pF, 50V, NPO, +/-5%, 0402, T=0.5mm", Manufacturer=YAGEO, Manufacturer_Part_Number=CC0402JRNPO9BN101, Package=0402
C16 C17: library part MCD-00324, "Capacitor, Tantalum, 10uF, 25V, 2R5, +/-10%, Type_B (3528 metric), T=1.9mm", Manufacturer=AVX, Manufacturer_Part_Number=TAJB106K025RNJ, Package="3528 (metric)"
C23 C24: library part MCD-01722, "Capacitor, MLCC, 1uF, 10V, X5R, +/-10%, 0402, T=0.5mm", Manufacturer=YAGEO, Manufacturer_Part_Number=CC0402KRX5R6BB105, Package=0402
CN1 CN2: library part MCD-02705, "Socket 25x2, 1.27mm, SMT, Height 2.29mm", Manufacturer=SAMTEC
CN3 CN4: library part MCD-00213, "Header, 19x2, 2.54mm, VR, TH, T=5.84mm/10.16mm", Manufacturer=SAMTEC, Manufacturer_Part_Number=TSW-119-09-G-D
CN5 CN8: library part MCD-01743, "Socket, 8x1, 2.54mm, VR, TH, T=8.51/2.64mm", Manufacturer=SAMTEC, Manufacturer_Part_Number=SSW-108-01-G-S
CN6: library part MCD-02080, "Socket, 10x1, 2.54mm, VR, TH, T=8.51/2.64mm", Manufacturer=SAMTEC, Manufacturer_Part_Number=SSW-110-01-G-S
CN7: library part MCD-02079, "Socket, 6x1, 2.54mm, VR, TH, T=8.51/2.64mm", Manufacturer=SAMTEC, Manufacturer_Part_Number=SSW-106-01-G-S
CN9: library part MCD-02421, "USB_TypeC, 24 pins, RA, SMD, T=3.71mm (USB Certified 3.1)", Manufacturer=MOLEX, Manufacturer_Part_Number=2012670005
CN10 CN11 CN12 CN13 CN14: library part MCD-00032, "Header, 2x1, 2.54mm, VR, TH, T=5.84mm/2.54mm", Manufacturer=SAMTEC, Manufacturer_Part_Number=TSW-102-07-G-S
HW2: library part MCD-02190, "Sticker board 25x5 mm", Manufacturer=N/A
JP1: library part MCD-01230, "Header, 5x2, 2.54mm, VR, SMD, T=5.84mm", Manufacturer=SAMTEC, Manufacturer_Part_Number=TSM-105-01-L-DV
JP2: library part MCD-01904, "Header, 2x1, 2.54mm, VR, TH, T=5.84mm/2.54mm", Manufacturer=SAMTEC, Manufacturer_Part_Number=TSW-102-07-G-S
LD1: library part MCD-00584, "LED Blue, 0603 SMD, 3.3 V Forward Voltage", Manufacturer=VISHAY, Manufacturer_Part_Number=VLMB1300-GS08, Package="LED 0603"
LD2 LD4: library part MCD-00589, "LED Green, 0603 SMD, Fw Voltage = 2.8V - 3.6V", Manufacturer=VISHAY, Manufacturer_Part_Number=VLMTG1300-GS08, Package="LED 0603"
LD3: library part MCD-00587, "LED Red, 0603 SMD, 2V Forward Voltage", Manufacturer=VISHAY, Manufacturer_Part_Number=VLMS1300-GS08, Package="LED 0603"
M1: library part MCD-01983, "STLINK-V3MODS module", Manufacturer=STMICROELECTRONICS, Manufacturer_HQ_COO=EU
R1 R4 R5 R10 R13: library part MCD-00061, "Resistor, 1K, 0402, +/-1%,1/16W", Manufacturer=YAGEO, Manufacturer_Part_Number=RC0402FR-071KL, Package=0402
R2 R3 R9: library part MCD-00053, "Resistor, 10K, 0402, +/-1%, 1/16W", Manufacturer=YAGEO, Manufacturer_Part_Number=RC0402FR-0710KL, Package=0402
R6 R7 R8: library part MCD-00507, "Resistor, 680R, 0402, +/-1%, 1/16W", Manufacturer=YAGEO, Manufacturer_Part_Number=RC0402FR-07680RL, Package=0402
R11 R12: library part MCD-00333, "Resistor, 5K1, 0402, +/-1%, 1/16W", Manufacturer=YAGEO, Manufacturer_Part_Number=RC0402FR-075K1L, Package=0402
R14: library part MCD-00119, "Resistor, 100R, 0402, +/-1%, 1/16W", Manufacturer=YAGEO, Manufacturer_Part_Number=RC0402FR-07100RL, Package=0402
R15 R16 R17 R18 R19 R20 R21 R22 R23 R24 R25 R26 R27 R28 R29 R30 R31: library part MCD-00059, "Resistor, 100K, 0402, +/-1%, 1/16W", Manufacturer=YAGEO, Manufacturer_Part_Number=RC0402FR-07100KL, Package=0402
SB1 SB2 SB3 SB4 SB5 SB6 SB9 SB10 SB11 SB15 SB17 SB18: library part MCD-01618, "Solder Bridge 0402 ON", Manufacturer=YAGEO, Manufacturer_Part_Number=RC0402JR-070RL, Package=SB0402
SB7 SB8 SB12 SB13 SB14 SB16 SB19 SB20 SB21 SB22: library part MCD-02162, "Solder Bridge 0402 OFF", Manufacturer=YAGEO, Manufacturer_Part_Number=RC0402JR-070RL, Package=SB0402
SW1: library part MCD-02081, "Switch-Slider, 3x1, 1.5mm, RA, SMD, T= 1.65mm", Manufacturer="TE CONNECTIVITY", Manufacturer_Part_Number=MLL1200S
U1: library part MCD-00649, "Common mode filter with ESD protection for USB 2.0 interface", Manufacturer=STMICROELECTRONICS, Manufacturer_HQ_COO=EU
U2: library part MCD-01207, "High power Transient voltage suppressor:25V/35A EOS and ESD transients protection.", Manufacturer=STMICROELECTRONICS, Manufacturer_HQ_COO=EU, Manufacturer_Part_Number=ESDA25P35-1U1M, Package=QFN1610
U3: library part MCD-00088, "IC REG LDO 5V 0.8A SOT223", Manufacturer=STMICROELECTRONICS, Manufacturer_HQ_COO=EU, Package=SOT-223
U4: library part MCD-00215, "Low quiescent current and low noise voltage regulators", Manufacturer=STMICROELECTRONICS, Manufacturer_HQ_COO=EU, Package="DFN6 3x3mm"
U5: library part MCD-00086, "Ultra low drop-low noise BiCMOS voltage, regulators low ESR capacitors compatible", Manufacturer=STMICROELECTRONICS, Manufacturer_HQ_COO=EU
U6 U7: library part MCD-01945, "4-bit dual supply translating transceiver with configurable voltage translation; 3-state", Manufacturer=NEXPERIA, Manufacturer_Part_Number=74AVC4TD245BQ,115, Package=DHVQFN16
? ?: library part MCD-01965

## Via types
v1: diameter 0.8, hole 0.3, Top Layer to Bottom Layer, tented both sides, 485 vias

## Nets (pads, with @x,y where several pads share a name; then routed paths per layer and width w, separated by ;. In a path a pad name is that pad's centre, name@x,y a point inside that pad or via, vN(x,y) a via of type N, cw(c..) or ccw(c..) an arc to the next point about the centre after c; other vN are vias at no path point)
3V3: C21.2 C22.2 CN3.16 CN5.4 SB19.2 SW1.1 U4.4 | length 97.5
  Top Layer w0.5: CN3.16@-58.42,-17.78 CN5.4@-53.34,-17.78 -51.892,-17.78 -50.343,-16.231 -50.343,-16.104 v1(-50.292,-16.154) ; v1(-43.104,-13.665) -41.237,-13.665 -40.907,-13.335 -37.833,-13.335 -37.503,-13.665 v1(-35.636,-13.665) v1@-35.611,-13.665
  Top Layer w0.6: v1(-45.745,-39.218) -45.161,-39.802 -41.91,-39.802 -41.402,-40.31 v1(-41.402,-40.513)
  Bottom Layer w0.254: -41.402,-42.596 -35.89,-42.596 -35.204,-41.91 -35.204,-39.421 -34.214,-38.43 -33.198,-38.43 -32.258,-39.37 -32.258,-40.767 -30.912,-42.113 -23.845,-42.113 -22.455,-40.723 SB19.2@-22.455,-39.446
  Bottom Layer w0.5: v1@-50.292,-16.18 v1(-50.292,-16.154) -50.292,-14.224 -49.043,-12.975 -45.293,-12.975 -44.552,-13.716 -44.552,-32.969 -45.771,-34.188 -45.771,-39.192 v1(-45.745,-39.218) ; -44.552,-13.675 -43.114,-13.675 v1(-43.104,-13.665) ; U4.4@-35.671,-7.605 -35.671,-10.055 C21.2@-35.419,-10.308 -35.636,-10.525 v1(-35.636,-13.665)
  Bottom Layer w0.6: SW1.1@-44.35,-46.509 -41.402,-43.561 -41.402,-42.596 v1(-41.402,-40.513)
3V3_STLK: C24.2 C25.2 C28.1 C30.1 R15.2 R16.2 R17.2 R18.2 R23.2 R24.2 R25.2 R26.2 U5.5 U6.1 U6.10 U6.15 U7.1 U7.10 U7.15 | length 70.8
  Top Layer w0.254: R24.2@-37.329,-27.751 -37.809,-27.751 -38.329,-28.27 -38.329,-31.664 -38.117,-31.876 -35.584,-31.876 R26.2@-35.564,-31.895 ; R24.2@-37.229,-27.651 -34.855,-27.651 R23.2@-34.846,-27.642 -34.33,-27.126 v1(-33.419,-27.126) ; R17.2@-36.122,-21.474 -35.433,-21.474 ; -35.784,-32.114 -35.738,-32.16 v1(-35.738,-32.537) ; v1(-35.484,-22.073) -35.484,-21.525 -35.433,-21.474 ; R18.2@-34.76,-21.459 -34.87,-21.459 -34.885,-21.474 -35.433,-21.474 ; C30.1@-33.485,-26.336 -33.485,-27.059 v1(-33.419,-27.126) ; C28.1@-32.599,-16.656 -32.04,-17.215 U6.1@-32.04,-17.591 ; U7.1@-32.44,-27.93 -32.44,-27.246 -32.56,-27.126 v1(-33.419,-27.126) ; U7.10@-30.99,-30.88 -30.731,-30.88 v1(-30.214,-31.397) v1@-30.214,-31.598 ; U7.15@-30.99,-28.38 -30.348,-28.38 -30.214,-28.247 v1(-30.214,-27.863) ; U6.10@-30.59,-20.541 -30.353,-20.541 -30.353,-21.488 v1(-30.404,-21.539) ; U6.15@-30.59,-18.041 -30.505,-17.957 v1(-30.505,-17.45) ; U5.5@-19.402,-29.664 U5.5@-19.278,-29.788
  Top Layer w0.5: C28.1@-32.614,-16.642 v1(-32.614,-15.875) ; v1@-30.214,-31.598 -30.214,-31.939 -29.947,-32.207 -25.908,-32.207 -24.486,-33.63 -19.558,-33.63 -18.694,-32.766 -18.694,-30.371 -19.278,-29.788 U5.5@-19.848,-29.788 ; U5.5@-19.402,-29.664 C24.2@-19.402,-28.575 C25.2@-19.402,-27.643
  Bottom Layer w0.254: v1(-35.484,-22.073) v1(-35.484,-17.805) -35.128,-17.45 v1(-30.505,-17.45) -30.505,-21.438 v1(-30.404,-21.539) -30.404,-22.504 -32.234,-24.335 -32.234,-27.126 ; v1(-33.419,-27.126) -32.234,-27.126 ; v1(-30.214,-31.397) -31.283,-30.328 -31.283,-29.074 -30.214,-28.005 v1(-30.214,-27.863) -31.497,-27.863 -32.234,-27.126
  Bottom Layer w0.5: -32.614,-17.297 v1(-32.614,-15.875)
5V: C19.2 C20.2 CN3.18 CN5.5 JP1.1 JP1.3 JP1.5 JP1.7 JP1.9 R13.2 U4.1 U4.6 | length 119
  Top Layer w0.5: CN3.18@-58.42,-20.32 CN5.5@-53.34,-20.32 ; v1(-54.458,-1.905) -54.445,-1.918 -54.445,-4.305 v1(-53.137,-5.613) ; v1(-49.098,-42.723) -47.117,-40.742 -42.596,-40.742 -39.167,-44.171 -37.592,-44.171 -37.553,-44.132 JP1.1@-37.368,-44.132 ; JP1.9@-27.208,-42.621 -27.229,-42.642 -27.229,-44.094 -24.994,-44.094 -24.6,-43.701 R13.2@-24.6,-42.352
  Top Layer w0.6: v1(-41.377,-0.787) -39.3,-2.864 v1(-36.545,-2.864)
  Top Layer w0.686: JP1.1@-37.368,-44.132 JP1.9@-27.257,-44.132
  Bottom Layer w0.254: -35.671,-4.978 -33.426,-4.978 -33.071,-5.333 U4.1@-33.071,-5.705
  Bottom Layer w0.3: -53.775,-41.9 -52.475,-41.9
  Bottom Layer w0.5: -53.775,-41.9 -54.6,-41.9 -55.85,-40.65 -55.85,-28.596 -54.991,-27.737 -54.991,-20.627 -54.684,-20.32 CN5.5@-53.34,-20.32 -51.714,-18.694 -51.714,-8.839 -53.137,-7.417 v1(-53.137,-5.613) ; -52.475,-41.9 -51.894,-41.9 -51.072,-42.723 v1(-49.098,-42.723)
  Bottom Layer w0.6: v1(-54.458,-1.905) -54.051,-1.499 -54.051,2.489 -52.578,3.962 -43.231,3.962 -41.377,2.108 v1(-41.377,-0.787) ; v1(-36.545,-2.864) C19.2@-35.521,-2.864 -35.671,-3.014 C20.2@-35.671,-4.332 -35.671,-4.978 U4.6@-35.671,-5.705
5V_EXT: CN3.6 JP1.10 | length 77.4
  Top Layer w0.6: v1(-42.85,-5.004) -38.964,-5.004 -37.643,-6.325 -27.457,-6.325 -25.171,-8.611 v1(-22.885,-8.611) ; JP1.10@-27.208,-37.671 -27.208,-36.139 -26.909,-35.839 -19.38,-35.839 v1(-18.948,-35.408)
  Bottom Layer w0.6: CN3.6@-58.42,-5.08 -55.601,-5.08 -54.661,-4.14 -51.283,-4.14 -50.673,-4.75 -46.711,-4.75 -46.457,-5.004 v1(-42.85,-5.004) ; v1(-22.885,-8.611) -22.885,-9.423 -21.59,-10.719 -21.59,-12.192 -21.082,-12.7 -21.082,-19.253 -19.888,-20.447 -19.888,-25.933 -17.628,-28.194 -17.628,-34.087 v1(-18.948,-35.408)
5V_INT: C17.1 JP1.6 R1.2 U3.2 U3.4 | length 53.7
  Top Layer w0.6: JP1.6@-32.288,-37.671 -32.288,-36.098 -31.318,-35.128 -27.661,-35.128 -27.483,-34.95 v1(-20.396,-34.95)
  Bottom Layer w0.254: U3.2@-28.788,-6.173 U3.2@-28.671,-6.057
  Bottom Layer w0.5: R1.2@-30.397,-6.173 U3.2@-28.788,-6.173
  Bottom Layer w0.6: U3.2@-28.671,-6.057 -28.646,-6.031 -24.246,-6.031 ; U3.4@-22.347,-6.031 -24.246,-6.031 ; v1(-20.396,-34.95) -19.025,-33.579 -19.025,-28.016 -20.676,-26.365 -20.676,-20.853 -21.971,-19.558 -21.971,-15.392 -24.246,-13.117 C17.1@-24.246,-11.567 -24.246,-6.031
5V_STLK: C23.2 C26.2 JP1.2 M1.22 U5.1 U5.3 | length 27.2
  Top Layer w0.2: U5.3@-21.896,-31.764 -21.325,-31.764 -20.853,-31.293 -20.853,-30.048 -21.037,-29.864 U5.1@-21.896,-29.864
  Top Layer w0.5: JP1.2@-37.368,-37.671 -37.368,-35.69 -36.4,-34.722 -32.588,-34.722 -32.029,-34.163 v1(-28.397,-34.163) ; v1(-23.546,-28.159) -22.572,-28.159 -22.563,-28.169 C26.2@-22.563,-28.55 U5.1@-22.563,-29.787
  Bottom Layer w0.5: v1(-28.397,-34.163) -28.397,-34.036 -26.314,-31.953 -26.314,-28.499 -25.975,-28.159 M1.22@-24.858,-28.159 v1(-23.546,-28.159)
5V_USB_MCU: C15.2 CN4.8 CN9.A4 CN9.A9 CN9.B4 CN9.B9 JP1.4 U2.1 | length 94.3
  Top Layer w0.6: JP1.4@-34.828,-37.671 -34.828,-38.756 v1(-33.719,-39.866) ; v1(-15.642,-43.708) -15.642,-44.403 -14.935,-45.11 -13.614,-45.11 -12.892,-44.388 v1(-12.892,-43.65) -11.178,-41.935 v1(-10.262,-41.935) ; v1(-7.747,-43.256) -7.849,-43.256 -7.391,-43.713 -7.391,-46.175 -6.043,-47.523 v1(-1.016,-47.523)
  Bottom Layer w0.3: U2.1@-18.1,-41.525 U2.1@-17.975,-41.4 ; C15.2@-16.87,-41.4 C15.2@-16.65,-41.4 ; CN9.B4@-15.642,-44.518 v1(-15.642,-43.708) ; CN9.B9@-13.142,-44.518 -13.142,-43.942 -12.892,-43.692 v1(-12.892,-43.65) CN9.A4@-12.892,-42.818
  Bottom Layer w0.5: C15.2@-16.65,-41.4 -15.892,-42.158 -15.892,-42.818 -15.892,-43.458 v1(-15.642,-43.708)
  Bottom Layer w0.6: v1(-33.719,-39.866) -33.719,-41.312 -31.978,-43.053 -23.737,-43.053 -23.433,-42.748 -22.936,-42.748 -21.713,-41.525 U2.1@-18.1,-41.525 ; U2.1@-17.975,-41.4 C15.2@-16.87,-41.4 ; v1@-10.287,-41.935 v1(-10.262,-41.935) -9.068,-41.935 v1(-7.747,-43.256) ; v1(-1.016,-47.523) 3.124,-47.523 4.064,-46.584 4.064,-9.144 CN4.8@2.54,-7.62
B1: R4.2 SB2.2 | length 53.6
  Top Layer w0.254: v1(-47.142,-43.053) -47.117,-43.053 -46.406,-43.764 -46.406,-44.059 R4.2@-46.141,-44.324 ; v1(-47.142,-36.652) -44.171,-36.652 -43.79,-37.033 -42.281,-37.033 -41.9,-36.652 -40.081,-36.652 -39.675,-36.246 -39.675,-33.782 -38.532,-32.639 -37.186,-32.639 -36.601,-33.223 -35.382,-33.223 -35.154,-32.995 -27.737,-32.995 -27.432,-32.69 -26.365,-32.69 -24.892,-34.163 -19.043,-34.163 -18.161,-35.045 -18.161,-36.601 -17.755,-37.008 -11.049,-37.008 v1(-9.884,-38.173)
  Bottom Layer w0.254: v1(-47.142,-43.053) v1(-47.142,-36.652) v1@-47.142,-36.551 ; v1@-9.982,-38.075 v1(-9.884,-38.173) SB2.2@-9.884,-39.147
B2: R5.2 SB4.2 | length 39.5
  Top Layer w0.254: R5.2@-41.408,-44.869 -41.135,-44.869 -40.335,-45.669 v1(-40.335,-45.644) ; v1(-23.317,-43.764) -22.911,-44.171 -21.714,-44.171 -21.203,-43.66 -21.203,-40.011 -21.641,-39.573 -21.641,-38.1 -21.057,-37.516 -11.782,-37.516 v1(-11.122,-38.176)
  Bottom Layer w0.254: v1(-40.335,-45.644) -39.662,-44.971 -39.061,-44.971 -38.82,-44.729 -24.282,-44.729 v1(-23.317,-43.764) ; SB4.2@-11.123,-39.172 -11.123,-38.178 v1(-11.122,-38.176)
B3: R10.2 SB6.2 | length 29.4
  Top Layer w0.254: R10.2@-33.539,-45.232 -33.387,-45.08 -21.845,-45.08 -20.803,-44.038 -20.803,-39.675 -21.184,-39.294 -21.184,-38.379 -20.701,-37.897 -13.056,-37.897 -12.471,-38.481 v1(-12.471,-38.204)
  Bottom Layer w0.254: SB6.2@-12.471,-39.138 v1(-12.471,-38.204)
GND: B1.1 B1.3 B2.1 B2.3 B3.1 B3.3 B4.1 B4.3 C1.1 C2.1 C3.1 C4.1 C5.1 C6.1 C7.1 C8.1 C9.1 C10.1 C11.1 C12.1 C13.1 C14.1 C15.1 C16.2 C17.2 C18.1 C19.1 C20.1 C21.1 C22.1 C23.1 C24.1 C25.1 C26.1 C27.1 C28.2 C29.1 C30.2 C31.1 CN1.1 CN1.6 CN1.7 CN1.14 CN1.17 CN1.22 CN1.25 CN1.28 CN1.31 CN1.34 CN1.37 CN1.40 CN1.46 CN1.49 CN2.2 CN2.8 CN2.14 CN2.20 CN2.26 CN2.32 CN2.38 CN2.44 CN2.50 CN3.8 CN3.19 CN3.20 CN3.22 CN4.9 CN4.20 CN4.32 CN5.6 CN5.7 CN6.7 CN9.A1 CN9.A12 CN9.B1 CN9.B12 CN9.SH1 CN9.SH2 CN9.SH3 CN9.SH4 CN10.2 CN11.2 CN12.1 CN12.2 CN13.1 CN13.2 CN14.2 LD4.2 M1.8 M1.24 M1.26 M1.27 M1.29 R11.1 R12.1 R14.1 R31.2 SW1.0 U1.3 U2.2 U3.1 U4.2 U4.EP U5.2 U6.2 U6.7 U6.8 U6.9 U6.17 U7.2 U7.8 U7.9 U7.17 | length 61.5
  Top Layer w0.254: v1(-33.964,-27.847) U7.2@-33.431,-28.38 ; v1(-33.435,-31.718) -33.047,-31.33 U7.8@-32.44,-31.33
  Top Layer w0.5: CN3.19@-60.96,-22.86 CN3.20@-58.42,-22.86 CN5.6@-53.34,-22.86 ; v1(-49.479,0.025) -49.479,0 CN1.1@-48.225,0 ; v1(-49.403,-30.455) -49.378,-30.48 CN1.49@-48.225,-30.48 ; v1(-49.403,-19.05) CN1.31@-48.225,-19.05 ; v1(-49.403,-10.16) CN1.17@-48.225,-10.16 ; v1(-49.378,-22.885) -49.352,-22.86 CN1.37@-48.225,-22.86 -46.94,-22.86 -45.67,-24.13 CN1.40@-44.485,-24.13 ; v1(-49.352,-3.81) CN1.7@-48.225,-3.81 -47.092,-3.81 v1(-45.822,-2.54) CN1.6@-44.485,-2.54 ; CN1.25@-48.225,-15.24 -48.21,-15.225 v1(-47.117,-15.225) ; CN1.34@-44.485,-20.32 v1(-43.282,-20.32) v1@-43.256,-20.32 ; CN1.28@-44.485,-16.51 -43.256,-16.51 v1(-43.282,-16.485) ; CN1.22@-44.485,-12.7 -43.256,-12.7 v1(-43.282,-12.675) ; CN1.14@-44.485,-7.62 -43.282,-7.62 v1(-43.282,-7.595) ; R31.2@-34.491,-31.892 -33.61,-31.892 v1(-33.435,-31.718) ; v1(-34.414,-25.522) -34.385,-25.551 C30.2@-34.385,-26.336 ; v1(-30.089,-25.572) -30.06,-25.601 C31.1@-30.06,-26.362 ; v1(-11.4,-26.67) CN2.44@-10.195,-26.67 ; v1(-11.4,-22.675) -11.215,-22.86 CN2.38@-10.195,-22.86 ; CN2.50@-10.195,-30.48 -10.175,-30.5 v1(-10.175,-31.35) ; CN2.32@-10.195,-19.05 v1(-8.944,-19.05) ; CN2.26@-10.195,-15.24 -8.92,-15.24 v1(-8.905,-15.225) ; CN2.20@-10.195,-11.43 -8.949,-11.43 v1(-8.944,-11.425) ; CN2.14@-10.195,-7.62 -7.755,-7.62 -6.739,-8.636 CN6.7@-5.08,-8.636 -2.989,-8.636 -1.465,-10.16 CN4.9@0,-10.16 ; CN2.8@-10.195,-3.81 v1(-8.944,-3.81) ; CN2.2@-10.195,0 v1(-8.85,0) v1@-8.775,0
  Bottom Layer w0.5: CN3.22@-58.42,-25.4 CN3.20@-58.42,-22.86 ; CN5.7@-53.34,-25.4 CN5.6@-53.34,-22.86 ; U4.EP@-34.371,-6.655 U4.2@-33.071,-6.655
  other v1: -41.123,-49.709 -38.938,-49.709 -36.195,-49.709 -32.715,-49.709 -30.96,-49.709 -27.94,-49.709 -24.246,-49.709 -17.442,-49.709 -14.642,-49.709 -11.709,-49.709 -7.747,-49.709 -32.004,-48.793 -11.049,-48.59 -6.579,-48.559 -52.603,-47.988 -58.42,-47.93 -55.88,-47.93 -35.941,-47.93 -27.788,-47.904 -62.459,-47.879 4.826,-47.523 -45.263,-47.396 -31.013,-47.222 -38.938,-47.193 -32.842,-47.193 -59.69,-46.736 -57.15,-46.634 1.295,-46.634 -1.168,-46.584 -3.353,-46.431 -31.928,-46.355 -24.587,-46.304 -49.784,-46.025 -45.593,-45.822 -63.5,-45.72 -17.374,-45.669 -6.579,-45.466 -20.879,-45.11 -2.591,-44.755 -44.374,-44.425 5.08,-44.425 -51.105,-44.374 -55.423,-43.866 -3.81,-43.84 -17.425,-43.675 -11.317,-43.683 -38.557,-43.332 -36.043,-43.282 -63.5,-43.129 -33.553,-43.129 -55.397,-42.52 -3.175,-42.52 -40.081,-41.961 -38.684,-41.961 5.08,-41.91 -36.119,-41.3 -63.5,-40.64 -47.803,-40.361 -30.988,-40.234 -36.195,-40.183 -37.871,-40.132 -3.734,-40.005 -46.355,-39.929 -16.764,-39.548 -14.935,-39.446 5.08,-39.421 -0.762,-39.345 -3.734,-38.735 -13.716,-38.557 -19.05,-38.532 -63.5,-38.1 -36.119,-37.719 -6.452,-37.617 -3.759,-37.44 -33.553,-37.313 5.08,-36.825 -19.152,-36.754 1.372,-36.551 -28.473,-36.373 -46.761,-35.611 -63.5,-35.56 -33.553,-35.56 -35.992,-35.535 -14.808,-35.382 -13.132,-35.382 -11.278,-35.281 -6.985,-34.849 5.08,-34.29 -12.344,-34.239 -37.008,-33.909 -1.524,-33.655 -63.5,-33.02 -22.327,-32.868 -9.22,-32.69 -42.012,-32.578 -48.1,-32.553 -1.524,-32.385 -31.189,-31.767 5.08,-31.767 -43.282,-31.547 -14.63,-31.471 -2.464,-30.963 -19.99,-30.709 -23.292,-30.658 -63.5,-30.455 -32.182,-30.15 5.08,-29.21 -32.156,-29.007 -1.626,-28.55 -20.98,-28.067 -63.5,-27.94 -43.358,-27.94 -3.556,-27.102 -16.485,-26.848 5.08,-26.695 -1.321,-26.568 -17.374,-25.959 -5.08,-25.883 -63.5,-25.425 -33.02,-25.425 -31.598,-25.375 -3.175,-25.121 5.08,-24.13 -32.944,-23.978 -45.999,-23.8 -30.302,-23.368 -31.979,-22.987 -36.195,-22.885 -34.771,-22.885 -63.5,-22.85 -29.032,-22.475 -33.122,-22.454 -17.272,-22.276 -31.191,-22.073 5.08,-21.539 -33.275,-21.311 -63.5,-20.32 -39.37,-20.066 -31.79,-19.939 5.08,-19.05 -31.775,-18.669 -63.5,-17.78 -37.668,-17.043 -39.573,-16.993 5.08,-16.485 -18.085,-16.002 -30.175,-15.926 -33.706,-15.824 -54.966,-15.494 -63.5,-15.215 -17.983,-14.275 -22.022,-13.97 5.08,-13.945 -34.214,-13.386 -32.487,-13.386 -63.5,-12.7 -15.367,-12.344 -22.631,-12.04 -54.813,-11.633 5.08,-11.455 -39.98,-10.998 -23.012,-10.541 -40.437,-10.308 -63.5,-10.16 -42.266,-10.16 -54.991,-10.008 -29.667,-9.652 -27.28,-9.525 -31.79,-9.5 -37.084,-9.246 -33.821,-9.068 5.08,-8.859 -15.24,-8.763 -38.659,-8.687 -37.795,-8.001 -20.904,-8.001 -63.5,-7.62 -8.905,-7.595 -31.79,-7.442 -36.545,-7.188 -25.349,-7.087 4.826,-6.35 -50.368,-6.248 -11.938,-6.093 -52.045,-5.639 -63.5,-5.08 -36.474,-5.08 -26.848,-4.978 -23.851,-4.877 -30.531,-4.648 -32.385,-4.547 -1.75,-4.42 -38.862,-3.81 -25.4,-3.81 4.826,-3.757 -42.672,-3.734 -11.582,-3.734 -22.86,-3.556 -50.216,-3.226 -20.632,-3.15 -52.705,-2.946 -24.003,-2.845 -26.848,-2.718 -63.5,-2.54 -42.672,-2.54 -19.888,-2.464 -16.942,-2.235 -55.499,-2.134 -49.708,-1.905 -38.329,-1.803 -30.302,-1.803 -32.258,-1.778 -35.357,-1.448 -22.53,-1.448 4.826,-1.225 -56.617,-1.168 -11.608,-0.94 -39.599,-0.889 -21.057,-0.508 -63.5,0 -7.468,0.025 -1.575,0.051 -37.186,0.203 -45.999,0.508 -22.504,0.508 -30.429,0.584 -34.828,0.61 -32.106,0.61 -56.769,0.635 -52.095,0.737 -25.654,0.762 -55.169,0.838 -50.038,1.016 -28.194,1.016 -47.676,1.041 -44.602,1.194 -14.808,1.245 4.826,1.27 -39.573,1.295 -12.852,1.372 -19.456,1.448 -60.96,1.727 1.778,2.032 -45.745,2.261 -7.112,2.261 -1.778,2.261 -10.414,2.286 -4.572,2.286 -58.344,2.413 -49.86,2.464 -47.676,2.489 -63.5,2.525 -20.65,2.692 -22.225,2.819 -36.652,2.921 -32.715,2.921 -13.892,2.921 -25.654,2.946 -40.64,2.972 -29.108,2.972 -43.942,3.048 -19.304,3.048 -16.002,3.048 -54.635,3.251 -17.526,3.556 4.826,3.81 -55.88,5.08 -53.34,5.08 -50.8,5.08 -48.26,5.08 -45.745,5.08 -43.256,5.08 -40.589,5.08 -38.1,5.08 -35.521,5.08 -33.02,5.08 -30.505,5.08 -27.989,5.08 -25.4,5.08 -22.86,5.08 -20.32,5.08 -17.78,5.08 -15.24,5.08 -12.7,5.08 -10.16,5.08 -7.62,5.08 -5.08,5.08 -2.591,5.08 1.524,5.588
GPIO0: CN1.3 CN3.1 | length 17.6
  Top Layer w0.254: CN3.1@-60.96,0 -59.26,1.7 -57.925,1.7 -57.1,2.525 v1(-51.025,2.525) ; v1(-51.005,-1.225) -51.05,-1.27 CN1.3@-48.225,-1.27
  Bottom Layer w0.254: v1(-51.025,2.525) -51.025,-1.205 v1(-51.005,-1.225)
GPIO1: CN1.5 CN3.3 | length 15.1
  Top Layer w0.254: CN3.3@-60.96,-2.54 -59.665,-1.245 -57.658,-1.245 -56.588,-0.175 -52.575,-0.175 -51.9,-0.85 -51.9,-1.625 -50.985,-2.54 CN1.5@-48.225,-2.54
GPIO2: CN1.8 CN3.2 | length 20.5
  Top Layer w0.254: CN3.2@-58.42,0 -58.42,0.205 -56.847,1.778 v1@-46.761,1.778 ; v1(-46.05,-4.039) -45.974,-4.115 -45.669,-3.81 CN1.8@-44.485,-3.81 CN1.8@-44.459,-3.835
  Bottom Layer w0.254: v1(-46.761,1.727) -46.812,1.778 -46.812,-3.277 v1(-46.05,-4.039)
GPIO3/BOOT0: CN1.9 CN3.7 | length 13.8
  Top Layer w0.254: CN3.7@-60.96,-7.62 -59.715,-6.375 -51.775,-6.375 -50.48,-5.08 CN1.9@-48.225,-5.08
GPIO4: CN1.10 CN3.4 | length 16.3
  Top Layer w0.254: CN3.4@-58.42,-2.54 -56.896,-2.54 -55.423,-1.067 -53.34,-1.067 -49.857,-4.55 -49.25,-4.55 -49.158,-4.458 -47.027,-4.458 -46.406,-5.08 CN1.10@-44.485,-5.08
GPIO5/JTMS/SWDIO: CN1.13 CN3.9 SB17.1 | length 43.5
  Top Layer w0.254: CN3.9@-60.96,-10.16 -59.65,-8.85 -57.775,-8.85 -57.175,-8.25 -57.175,-7.112 -56.794,-6.731 -50.829,-6.731 -49.94,-7.62 CN1.13@-48.225,-7.62 -47.981,-7.62 -46.05,-5.69 -39.878,-5.69 v1(-39.319,-6.248) ; v1(-39.319,-14.199) -37.973,-14.199 -37.821,-14.351 -35.128,-14.351 -34.849,-14.072 -30.328,-14.072 v1(-30.175,-13.919)
  Bottom Layer w0.254: v1(-39.319,-14.199) v1@-39.167,-14.199 ; v1(-39.319,-6.248) -39.319,-14.046 v1@-39.167,-14.199 ; v1@-39.141,-14.224 v1@-39.167,-14.199 ; v1(-30.175,-13.919) -30.157,-13.901 SB17.1@-29.386,-13.901
GPIO6/JTCK/SWCLK: CN1.15 CN3.11 SB15.1 | length 37.5
  Top Layer w0.254: CN3.11@-60.96,-12.7 -60.75,-12.7 -59.48,-11.43 -56.355,-11.43 -56.032,-11.107 -56.032,-9.652 -55.18,-8.8 CN1.15@-48.425,-8.8 ; CN1.15@-48.225,-8.89 -46.935,-8.89 -46.3,-9.525 -43.586,-9.525 -43.32,-9.258 -43.32,-8.954 -42.824,-8.458 -40.056,-8.458 -39.624,-8.89 -39.624,-10.236 -38.405,-11.455 v1(-29.515,-11.455)
  Bottom Layer w0.254: v1(-29.515,-11.455) -29.406,-11.346 SB15.1@-29.406,-10.608
GPIO7: CN1.16 CN3.26 | length 36.5
  Top Layer w0.254: v1(-56.82,-10.592) -56.82,-9.652 -55.418,-8.25 -46.843,-8.25 -46.203,-8.89 CN1.16@-44.485,-8.89
  Bottom Layer w0.254: CN3.26@-58.42,-30.48 -59.65,-29.25 -59.65,-27.325 -59.05,-26.725 -57.6,-26.725 -56.8,-25.925 v1@-56.8,-10.9 ; v1(-56.82,-10.592) v1@-56.543,-10.592
GPIO8: CN1.19 CN3.13 | length 14.3
  Top Layer w0.254: CN3.13@-60.96,-15.24 -59.69,-13.97 -52.07,-13.97 -49.53,-11.43 CN1.19@-48.225,-11.43
GPIO9: CN1.21 CN3.15 | length 15.7
  Top Layer w0.254: CN3.15@-60.96,-17.78 -59.68,-16.5 -51.755,-16.5 -50.14,-14.884 -50.14,-13.462 -49.378,-12.7 CN1.21@-48.225,-12.7
GPIO10: CN1.23 CN3.17 | length 16.7
  Top Layer w0.254: CN3.17@-60.96,-20.32 -59.69,-19.05 -51.968,-19.05 -49.53,-16.612 -49.53,-14.249 -49.251,-13.97 CN1.23@-48.225,-13.97
GPIO11: CN1.24 CN3.28 CN7.1 | length 30.6
  Top Layer w0.254: CN3.28@-58.42,-33.02 CN7.1@-53.34,-33.02 -50.698,-33.02 v1(-49.327,-31.648) ; v1@-45.72,-13.97 CN1.24@-44.485,-13.97
  Bottom Layer w0.254: v1@-49.4,-31.744 v1@-49.327,-31.671 ; v1(-49.327,-31.648) v1@-49.327,-31.671 ; v1(-45.618,-13.945) -46.327,-14.653 -46.327,-15.56 -45.974,-15.913 -45.974,-18.593 -48.336,-20.955 -48.336,-30.68 v1@-49.327,-31.671
GPIO12: CN1.26 CN3.30 CN7.2 | length 30.9
  Top Layer w0.254: CN3.30@-58.42,-35.56 CN7.2@-53.34,-35.56 -51.51,-35.56 -49.454,-33.504 v1(-49.454,-32.69) ; v1(-45.618,-15.215) -45.618,-15.282 -45.6,-15.3 -45.54,-15.24 CN1.26@-44.485,-15.24
  Bottom Layer w0.254: v1(-49.454,-32.69) -47.925,-31.161 -47.925,-21.128 -45.618,-18.821 v1(-45.618,-15.215)
GPIO13: CN1.27 CN3.21 | length 18.7
  Top Layer w0.254: CN3.21@-60.96,-25.4 -59.71,-24.15 -52.55,-24.15 -51.979,-23.579 -51.979,-19.67 -48.819,-16.51 CN1.27@-48.225,-16.51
